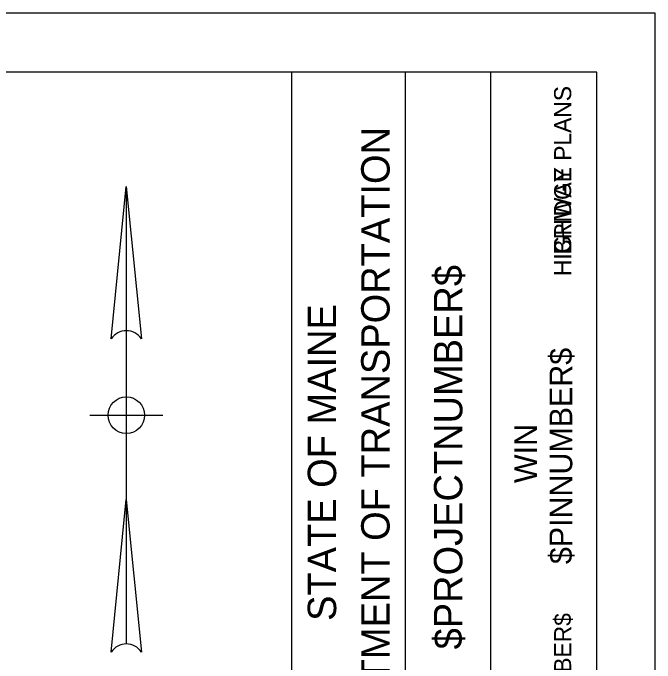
# Model space of a CAD drawing. Extents: x 916257 to 917115, y 329394 to 329944.
# Drawn here: x 917001.8 to 917107, y 329837.4 to 329943.9 of the extents above; entities that cross this region are included whole.
import ezdxf

# ---------------------------------------------------------------- set-up
doc = ezdxf.new("R2010")
doc.units = 0
for name, color, linetype in [('Border', 7, 'Continuous'), ('BRIDGE_TITLE', 7, 'Continuous'), ('H_V CONTROLS', 7, 'Continuous'), ('HIGHWAY_TITLE', 7, 'Continuous'), ('PLOT BOUNDARY', 7, 'Continuous')]:
    doc.layers.add(name, color=color, linetype=linetype)

msp = doc.modelspace()

# ---------------------------------------------------------------- linework, layer by layer
at = {"layer": 'Border'}
for p, q in [((917097.47, 329934.21), (916297.47, 329934.21)), ((917047.47, 329409.22), (917047.47, 329934.22)), ((917066.11, 329809.19), (917066.11, 329934.19)), ((917080.08, 329809.19), (917080.08, 329934.19)), ((917097.47, 329409.22), (917097.47, 329934.22))]:
    msp.add_line(p, q, dxfattribs=at)
at = {"layer": 'H_V CONTROLS'}
for p, q in [((917017.85, 329890.49), (917020.35, 329915.49)), ((917020.35, 329915.49), (917020.35, 329840.49)), ((917020.35, 329915.49), (917022.85, 329890.49)), ((917014.35, 329877.99), (917026.35, 329877.99)), ((917017.85, 329839.15), (917020.35, 329864.15)), ((917020.35, 329864.15), (917022.85, 329839.15))]:
    msp.add_line(p, q, dxfattribs=at)
msp.add_circle((917020.35, 329877.99), 3, dxfattribs=at)
for centre in [(917020.35, 329888.83), (917020.35, 329837.49)]:
    msp.add_arc(centre, 3, 33.5573, 146.4427, dxfattribs=at)
at = {"layer": 'PLOT BOUNDARY'}
msp.add_lwpolyline([(916257, 329393.91), (917107, 329393.91), (917107, 329943.91), (916257, 329943.91)], close=True, dxfattribs=at)

# ---------------------------------------------------------------- texts
at = {"layer": 'Border'}
for s, height, p in [('DEPARTMENT OF TRANSPORTATION', 4.6588, (917063.5, 329812.74)), ('$PROJECTNUMBER$', 4.6588, (917075.43, 329839.6)), ('STATE OF MAINE', 4.6588, (917054.74, 329844.27)), ('$PINNUMBER$', 3.7264, (917093.44, 329853.58)), ('WIN', 3.726, (917087.65, 329866.86))]:
    msp.add_text(s, height=height, rotation=90, dxfattribs=at).set_placement(p)
at = {"layer": 'BRIDGE_TITLE'}
for s, p in [('BRIDGE PLANS', (917093.26, 329904.33)), ('$BRIDGENUMBER$', (917093.26, 329810.86))]:
    msp.add_text(s, height=2.795, rotation=90, dxfattribs=at).set_placement(p)
at = {"layer": 'HIGHWAY_TITLE'}
msp.add_text('HIGHWAY PLANS', height=2.795, rotation=90, dxfattribs=at).set_placement((917093.26, 329900.79))

doc.saveas('drawing.dxf')
